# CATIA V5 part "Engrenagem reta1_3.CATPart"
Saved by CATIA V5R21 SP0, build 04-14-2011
Part number: Engrenagem reta1_3
Definition: Engrenagem reta1_3
Nomenclature: Engrenagem reta17
Source: Unknown
Bounding box of the stored display mesh (mm): x -0.99 to 0.99, y -0.989 to 0.989, z 0 to 1.25
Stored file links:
  C:\Users\beatr\OneDrive\Documents\UNB\2026_1\Pi1\Componentes eletronicos\Engrenagem reta1_3.CATPart
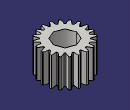
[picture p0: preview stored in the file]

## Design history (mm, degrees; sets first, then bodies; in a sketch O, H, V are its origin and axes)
Body1 "Solid1" (main body)
  Solid1: solid without history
